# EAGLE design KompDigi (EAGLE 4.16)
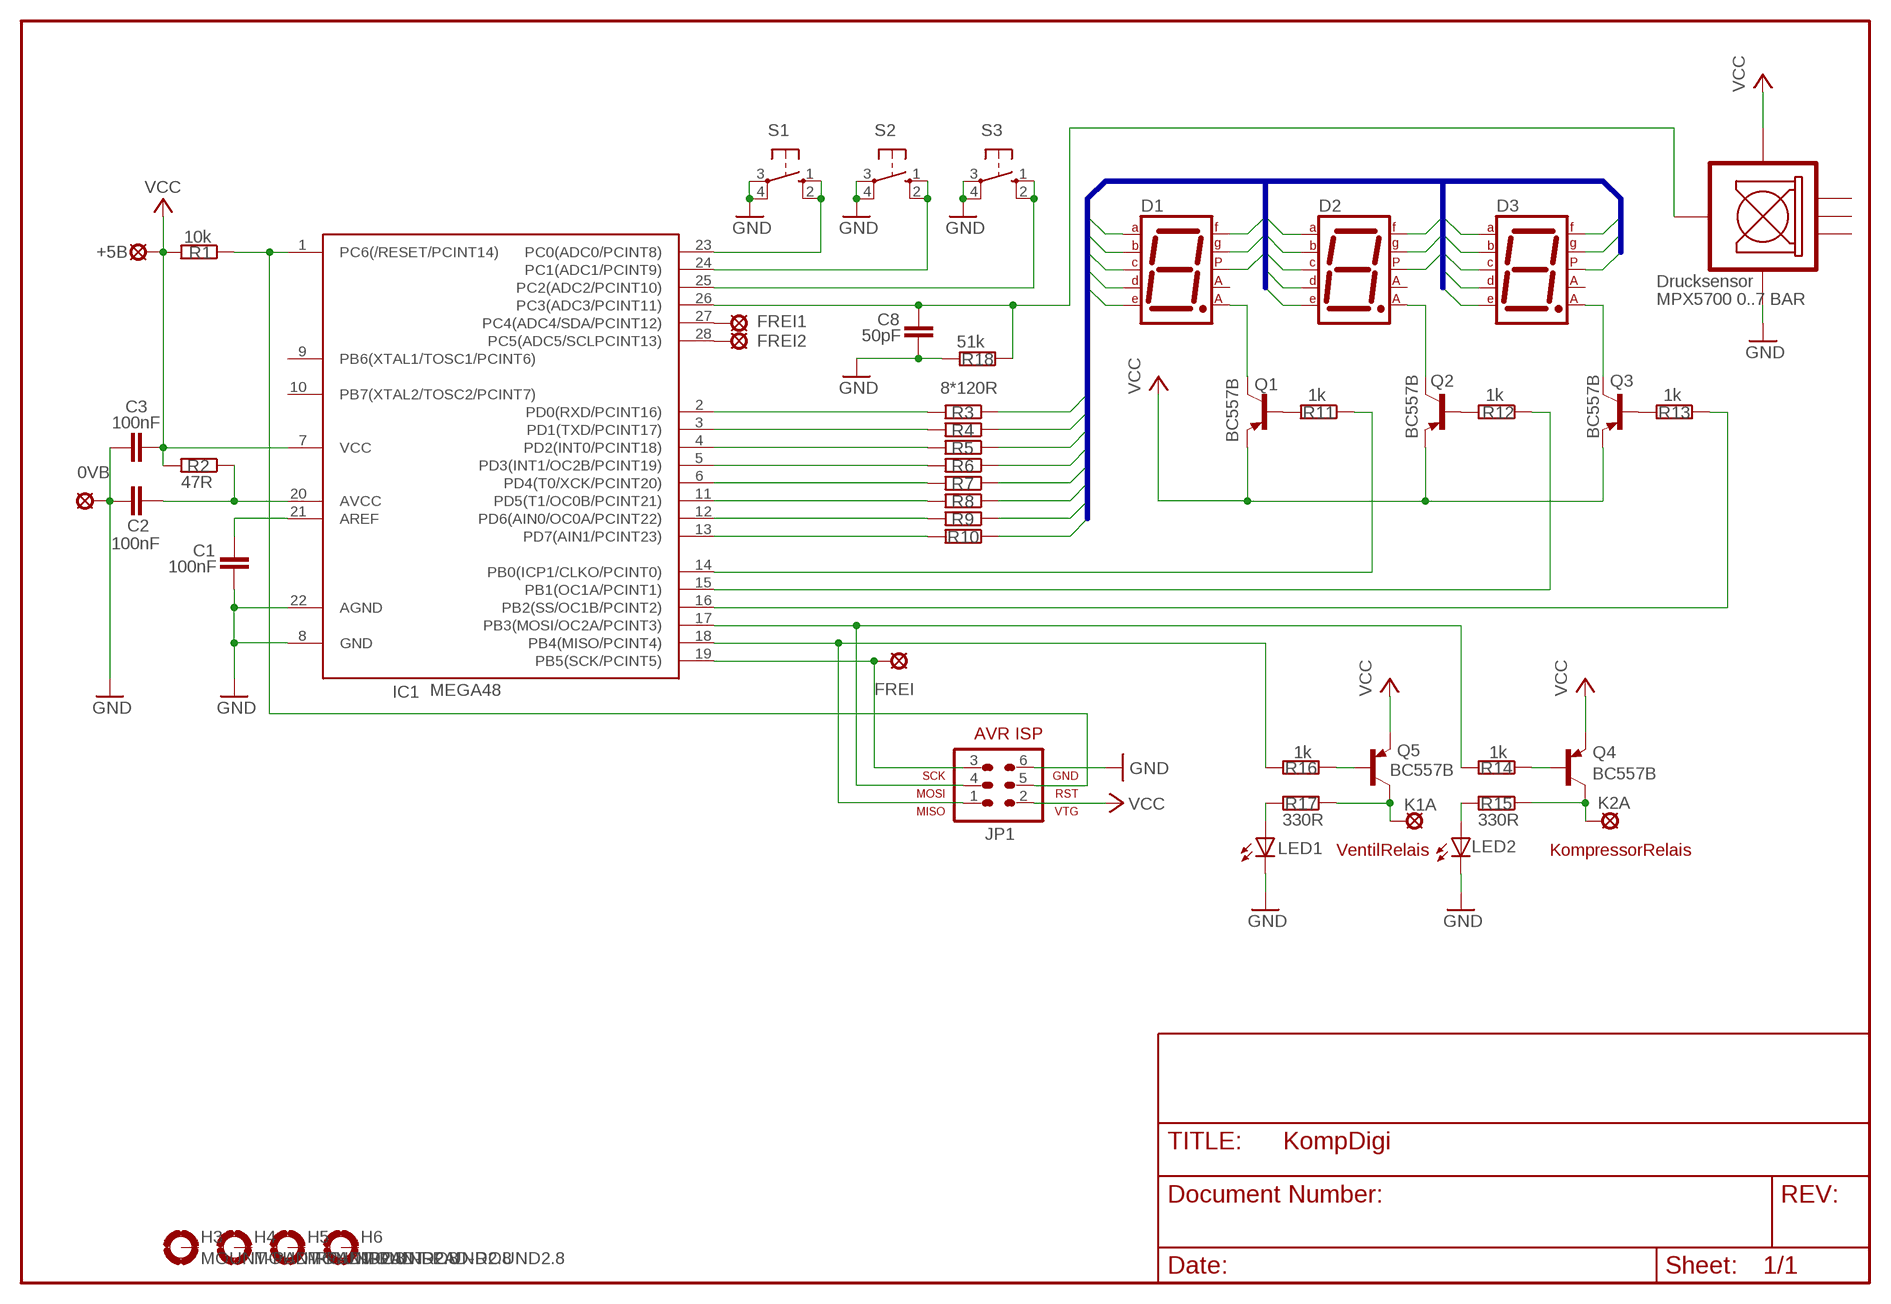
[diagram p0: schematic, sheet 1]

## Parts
0VB  LSP10  [LSP10]
+5B  LSP10  [LSP10]
C1  100nF  C-EU025-025X050  [C025-025X050]
C2  100nF  C-EU025-025X050  [C025-025X050]
C3  100nF  C-EU025-025X050  [C025-025X050]
C8  50pF  C-EU025-024X044  [C025-024X044]
D1  7SEG-CA  [7SEG-13]
D2  7SEG-CA  [7SEG-13]
D3  7SEG-CA  [7SEG-13]
DR1  MPX5700  MPX5700GS  [MPX5700GS]
FREI  LSP10  [LSP10]
FREI1  LSP10  [LSP10]
FREI2  LSP10  [LSP10]
H3  MOUNT-PAD-ROUND2.8  [2,8-PAD]
H4  MOUNT-PAD-ROUND2.8  [2,8-PAD]
H5  MOUNT-PAD-ROUND2.8  [2,8-PAD]
H6  MOUNT-PAD-ROUND2.8  [2,8-PAD]
IC1  MEGA48  MEGA48/88/168-PU  [DIL28-3]
JP1  AVR-ISP-6  [AVR-ISP-6]
K1A  LSP10  [LSP10]
K2A  LSP10  [LSP10]
LED1  LED3MM  [LED3MM]
LED2  LED3MM  [LED3MM]
Q1  BC557B  [TO92-EBC]
Q2  BC557B  [TO92-EBC]
Q3  BC557B  [TO92-EBC]
Q4  BC557B  [TO92-EBC]
Q5  BC557B  [TO92-EBC]
R1  10k  R-EU_0207/7  [0207/7]
R2  47R  R-EU_0207/7  [0207/7]
R3  R-EU_0207/7  [0207/7]
R4  R-EU_0207/7  [0207/7]
R5  R-EU_0207/7  [0207/7]
R6  R-EU_0207/7  [0207/7]
R7  R-EU_0207/7  [0207/7]
R8  R-EU_0207/7  [0207/7]
R9  R-EU_0207/7  [0207/7]
R10  R-EU_0207/7  [0207/7]
R11  1k  R-EU_0207/7  [0207/7]
R12  1k  R-EU_0207/7  [0207/7]
R13  1k  R-EU_0207/7  [0207/7]
R14  1k  R-EU_0207/7  [0207/7]
R15  330R  R-EU_0207/7  [0207/7]
R16  1k  R-EU_0207/7  [0207/7]
R17  330R  R-EU_0207/7  [0207/7]
R18  51k  R-EU_0207/7  [0207/7]
S1  10-XX  [B3F-10XX]
S2  10-XX  [B3F-10XX]
S3  10-XX  [B3F-10XX]

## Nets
A: D1.7(A) D2.7(A) D3.7(A) R3.1
B: D1.6(B) D2.6(B) D3.6(B) R4.1
C: D1.4(C) D2.4(C) D3.4(C) R5.1
D: D1.2(D) D2.2(D) D3.2(D) R6.1
DP: D1.5(DP) D2.5(DP) D3.5(DP) R10.1
E: D1.1(E) D2.1(E) D3.1(E) R7.1
F: D1.9(F) D2.9(F) D3.9(F) R8.1
G: D1.10(G) D2.10(G) D3.10(G) R9.1
GND: 0VB.MP C1.1 C2.1 C3.1 C8.1 DR1.2(GND) IC1.8(GND) IC1.22(AGND) JP1.6 LED1.K(C) LED2.K(C) R18.2 S1.3(P) S1.4(P1) S2.3(P) S2.4(P1) S3.3(P) S3.4(P1)
N$1: D1.8(CA2) Q1.C
N$2: D2.8(CA2) Q2.C
N$3: D3.8(CA2) Q3.C
N$4: C1.2 IC1.21(AREF)
N$5: C2.2 IC1.20(AVCC) R2.1
N$6: IC1.1(PC6(/RESET/PCINT14)) JP1.5 R1.1
N$7: IC1.2(PD0(RXD/PCINT16)) R3.2
N$8: IC1.3(PD1(TXD/PCINT17)) R4.2
N$9: IC1.4(PD2(INT0/PCINT18)) R5.2
N$10: IC1.5(PD3(INT1/OC2B/PCINT19)) R6.2
N$11: IC1.6(PD4(T0/XCK/PCINT20)) R7.2
N$12: IC1.11(PD5(T1/OC0B/PCINT21)) R8.2
N$13: IC1.12(PD6(AIN0/OC0A/PCINT22)) R9.2
N$14: IC1.13(PD7(AIN1/PCINT23)) R10.2
N$15: Q1.B R11.2
N$16: Q2.B R12.2
N$17: Q3.B R13.2
N$18: IC1.14(PB0(ICP1/CLKO/PCINT0)) R11.1
N$19: IC1.15(PB1(OC1A/PCINT1)) R12.1
N$20: IC1.16(PB2(SS/OC1B/PCINT2)) R13.1
N$21: IC1.17(PB3(MOSI/OC2A/PCINT3)) JP1.4 R14.2
N$22: IC1.18(PB4(MISO/PCINT4)) JP1.1 R16.2
N$23: FREI.MP IC1.19(PB5(SCK/PCINT5)) JP1.3
N$24: Q4.B R14.1
N$25: K2A.MP Q4.C R15.1
N$26: IC1.24(PC1(ADC1/PCINT9)) S2.1(S) S2.2(S1)
N$27: IC1.25(PC2(ADC2/PCINT10)) S3.1(S) S3.2(S1)
N$28: IC1.23(PC0(ADC0/PCINT8)) S1.1(S) S1.2(S1)
N$29: LED2.A R15.2
N$30: Q5.B R16.1
N$31: K1A.MP Q5.C R17.1
N$32: LED1.A R17.2
N$33: C8.2 DR1.1(OUT) IC1.26(PC3(ADC3/PCINT11)) R18.1
N$34: FREI1.MP IC1.27(PC4(ADC4/SDA/PCINT12))
N$35: FREI2.MP IC1.28(PC5(ADC5/SCLPCINT13))
VCC: +5B.MP C3.2 DR1.3(VCC) IC1.7(VCC) JP1.2 Q1.E Q2.E Q3.E Q4.E Q5.E R1.2 R2.2
Unconnected: D1.3(CA1) D2.3(CA1) D3.3(CA1) DR1.4(6NC) DR1.5(5NC) DR1.6(4NC) H3.B2,8(MOUNT) H4.B2,8(MOUNT) H5.B2,8(MOUNT) H6.B2,8(MOUNT) IC1.9(PB6(XTAL1/TOSC1/PCINT6)) IC1.10(PB7(XTAL2/TOSC2/PCINT7))

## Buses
SEG:A,B,C,D,E,F,G,DP

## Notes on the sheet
- Drucksensor
- MPX5700 0..7 BAR
- 8*120R
- VentilRelais | KompressorRelais

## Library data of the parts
0VB +5B FREI FREI1 FREI2 K1A K2A = solpad:LSP10: SOLDER PAD
C1-C3 C8 = rcl:C-EU: CAPACITOR, European symbol
D1-D3 = andereBauteile:7SEG-CA: 7-segment DISPLAY single anode, 13 mm
DR1 = mpx5700:MPX5700GS
H3-H6 = holes:MOUNT-PAD-ROUND: MOUNTING PAD, round
IC1 = avr-5-4.16:MEGA48/88/168-PU
JP1 = atmel (2):AVR-ISP-6: AVR ISP-6 Serial Programming Header
LED1 LED2 = led:LED: LED
Q1-Q5 = transistor-pnp:BC557*: PNP Transistror
R1-R18 = rcl:R-EU_: RESISTOR, European symbol
S1-S3 = switch-omron:10-XX: OMRON SWITCH

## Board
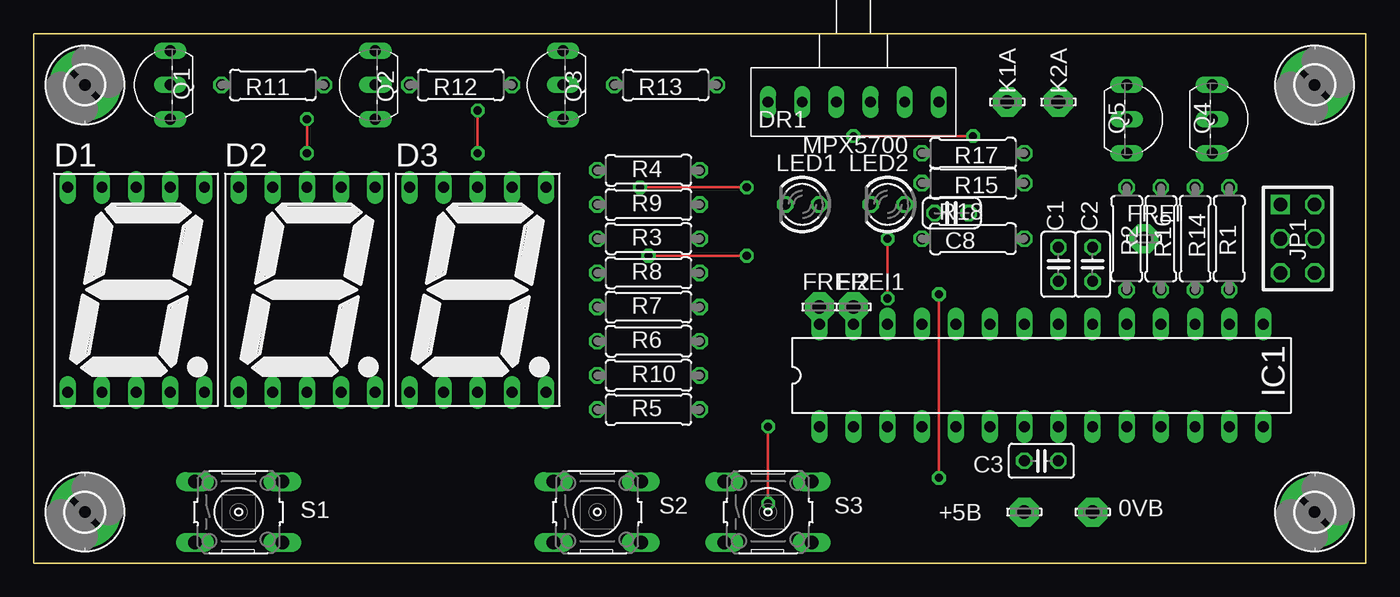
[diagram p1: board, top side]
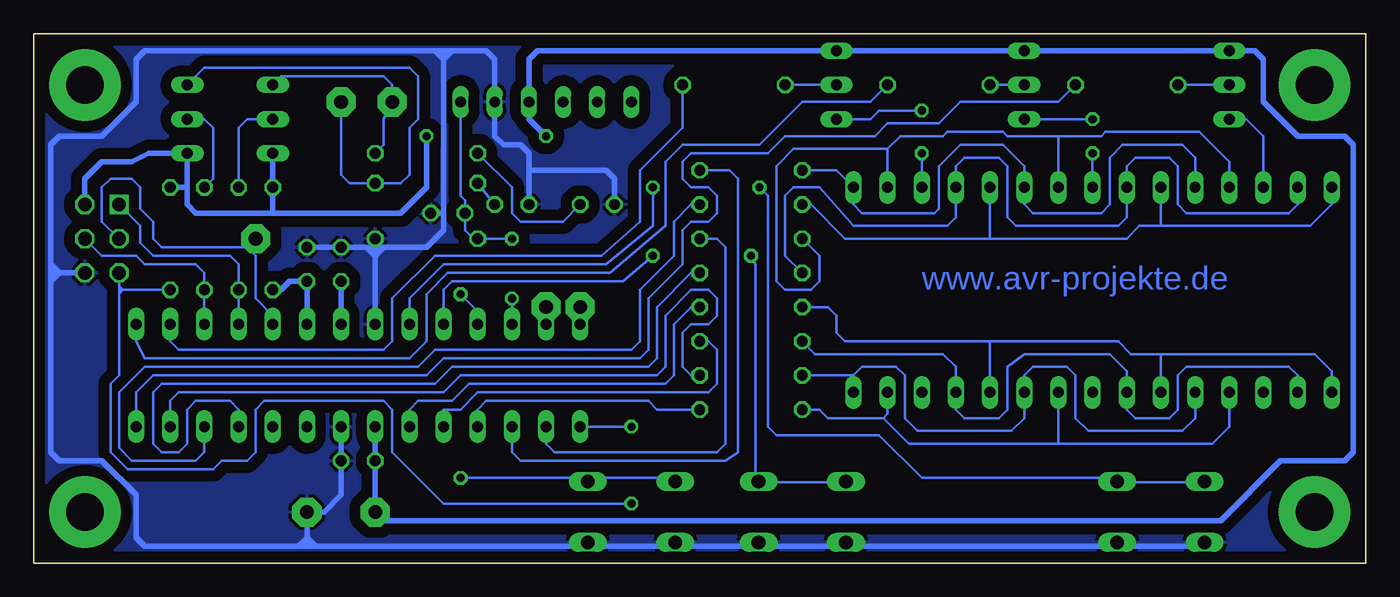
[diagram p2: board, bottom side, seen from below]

Size 99.06 x 39.37 mm. Coordinates in mm from the lower left corner, seen from the top.
Outline: 99.06,0 99.06,39.37 0,39.37 0,0 99.06,0
Copper layers (1*16): Top 0.035mm / dielectric 1.5mm / Bottom 0.035mm
Design rules "ZWILLING": minimum track width 0.2mm, minimum drill 0.5mm, track to track 0.2mm, track to pad 0.2mm, pad to pad 0.15mm, via to via 0.2mm, smd to smd 0mil, copper to edge 0.2mm, drill to drill 0.2mm, minimum pad ring 0.2mm, minimum via ring 0.2mm, stop-mask expansion 0.1mm, vias tented up to drill 0mil, thermal gap 10mil

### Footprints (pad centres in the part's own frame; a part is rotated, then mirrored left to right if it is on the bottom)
LSP10 = drill 1.016 pad 2.159 octagon: MP 0,0
C025-025X050 = drill 0.813 octagon: 1 -1.27,0; 2 1.27,0
C025-024X044 = drill 0.813 octagon: 1 -1.27,0; 2 1.27,0
7SEG-13 = drill 0.813 long: 1 -5.08,-7.62; 2 -2.54,-7.62; 3 0,-7.62; 4 2.54,-7.62; 5 5.08,-7.62; 6 5.08,7.62; 7 2.54,7.62; 8 0,7.62; 9 -2.54,7.62; 10 -5.08,7.62
MPX5700GS = drill 0.8 long: 1 6.35,0; 2 3.81,0; 3 1.27,0; 4 -1.27,0; 5 -3.81,0; 6 -6.35,0
2,8-PAD = drill 2.8 pad 5.334 round: B2,8 0,0
DIL28-3 = drill 0.813 long: 1 -16.51,-3.81; 2 -13.97,-3.81; 3 -11.43,-3.81; 4 -8.89,-3.81; 5 -6.35,-3.81; 6 -3.81,-3.81; 7 -1.27,-3.81; 8 1.27,-3.81; 9 3.81,-3.81; 10 6.35,-3.81; 11 8.89,-3.81; 12 11.43,-3.81; 13 13.97,-3.81; 14 16.51,-3.81; 15 16.51,3.81; 16 13.97,3.81; 17 11.43,3.81; 18 8.89,3.81; 19 6.35,3.81; 20 3.81,3.81; 21 1.27,3.81; 22 -1.27,3.81; 23 -3.81,3.81; 24 -6.35,3.81; 25 -8.89,3.81; 26 -11.43,3.81; 27 -13.97,3.81; 28 -16.51,3.81
AVR-ISP-6 = drill 1.016 square: 1 -2.54,-1.27 | drill 1.016 octagon: 2 -2.54,1.27; 3 0,-1.27; 4 0,1.27; 5 2.54,-1.27; 6 2.54,1.27
LED3MM = drill 0.813 octagon: A -1.27,0; K 1.27,0
TO92-EBC = drill 0.813 long: B 0,-1.27; C -2.54,-1.27; E 2.54,-1.27
0207/7 = drill 0.813 octagon: 1 -3.81,0; 2 3.81,0
B3F-10XX = drill 1.016 long: 1 -3.251,2.261; 2 3.251,2.261; 3 -3.251,-2.261; 4 3.251,-2.261

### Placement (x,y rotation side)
0VB  78.74,3.81 0 top
+5B  73.66,3.81 0 top
C1  76.2,22.23 270 top
C2  78.74,22.23 270 top
C3  74.93,7.62 180 top
C8  68.26,26.04 180 top
D1  7.62,20.32 0 top
D2  20.32,20.32 0 top
D3  33.02,20.32 0 top
DR1  60.96,34.29 0 top
FREI  82.55,24.13 0 top
FREI1  60.96,19.05 0 top
FREI2  58.42,19.05 0 top
H3  3.81,35.56 0 top
H4  3.81,3.81 0 top
H5  95.25,35.56 0 top
H6  95.25,3.81 0 top
IC1  74.93,13.97 0 top
JP1  93.98,24.13 270 top
K1A  72.39,34.29 0 top
K2A  76.2,34.29 0 top
LED1  57.15,26.67 180 top
LED2  63.5,26.67 180 top
Q1  8.89,35.56 90 top
Q2  24.13,35.56 90 top
Q3  38.1,35.56 90 top
Q4  88.9,33.02 270 top
Q5  82.55,33.02 270 top
R1  88.9,24.13 90 top
R2  81.28,24.13 90 top
R3  45.72,24.13 0 top
R4  45.72,29.21 0 top
R5  45.72,11.43 0 top
R6  45.72,16.51 0 top
R7  45.72,19.05 0 top
R8  45.72,21.59 0 top
R9  45.72,26.67 0 top
R10  45.72,13.97 0 top
R11  17.78,35.56 180 top
R12  31.75,35.56 180 top
R13  46.99,35.56 180 top
R14  86.36,24.13 270 top
R15  69.85,28.26 180 top
R16  83.82,24.13 270 top
R17  69.85,30.48 180 top
R18  69.85,24.13 0 top
S1  15.24,3.81 0 top
S2  41.91,3.81 0 top
S3  54.61,3.81 0 top

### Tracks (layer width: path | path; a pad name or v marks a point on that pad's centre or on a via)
A
  Bottom 0.203: D1.7 10.16,29.84 12.38,32.07 19.37,32.07 19.68,31.75 22.86,31.75 | 35.56,30.8 42.55,30.8 43.81,29.53 43.81,20.95 43.18,20.32 41.27,20.32 40.64,20.95 40.64,22.86 R3.1 | 35.56,30.8 D3.7 | 22.86,31.75 26.67,31.75 26.99,32.07 31.11,32.07 31.43,31.75 34.61,31.75 35.56,30.8 | 22.86,31.75 D2.7
B
  Bottom 0.203: D1.6 12.7,30.16 13.65,31.11 18.1,31.11 19.05,30.16 19.05,26.67 19.68,26.04 24.77,26.04 25.4,26.67 D2.6 25.4,29.53 26.99,31.11 30.16,31.11 31.75,29.53 31.75,26.35 32.07,26.04 37.47,26.04 38.1,26.67 D3.6 39.37,29.21 R4.1
C
  Bottom 0.203: D1.4 10.16,10.16 11.43,8.89 22.86,8.89 | 22.86,8.89 33.97,8.89 35.88,10.79 | 22.86,8.89 D2.4 | R5.1 40.64,11.43 40.01,10.79 35.88,10.79 | D3.4 35.56,11.11 35.88,10.79
D
  Bottom 0.203: D1.2 5.08,13.97 5.71,14.61 13.34,14.61 13.97,13.97 13.97,11.43 14.61,10.79 17.14,10.79 17.78,11.43 D2.2 17.78,14.29 19.05,15.56 25.4,15.56 26.67,14.61 26.67,11.43 27.3,10.79 29.84,10.79 30.48,11.43 D3.2 30.48,14.61 31.43,15.56 40.96,15.56 R6.1
DP
  Bottom 0.203: D1.5 12.7,10.79 13.65,9.84 20.64,9.84 21.59,10.79 21.59,13.97 22.23,14.61 24.77,14.61 25.4,13.97 D2.5 25.4,10.79 26.35,9.84 33.34,9.84 34.29,10.79 34.29,13.97 34.92,14.61 37.47,14.61 38.1,13.97 | 38.1,13.97 D3.5 | 38.1,13.97 R10.1
E
  Bottom 0.203: D1.1 2.54,14.29 3.81,15.56 15.24,15.56 | R7.1 40.01,19.05 39.37,18.41 39.37,17.14 38.73,16.51 27.94,16.51 | 15.24,15.56 17.46,15.56 18.41,16.51 27.94,16.51 | 27.94,16.51 D3.1 | 15.24,15.56 D2.1
F
  Bottom 0.203: D1.9 5.08,26.67 5.71,26.04 13.34,26.04 13.97,26.67 13.97,29.53 14.61,30.16 17.14,30.16 17.78,29.53 D2.9 17.78,25.72 18.41,25.08 26.04,25.08 26.67,25.72 26.67,29.53 27.3,30.16 29.84,30.16 30.48,29.53 D3.9 30.48,25.72 31.11,25.08 38.1,25.08 40.64,27.94 42.55,27.94 43.18,27.3 43.18,22.86 R8.1
G
  Bottom 0.203: D1.10 2.54,26.67 4.13,25.08 15.24,25.08 | 15.24,25.08 16.83,25.08 17.78,24.13 27.94,24.13 | 27.94,24.13 38.73,24.13 41.27,26.67 R9.1 | 27.94,24.13 D3.10 | 15.24,25.08 D2.10
GND
  Bottom 0.203: 78.11,1.27 78.74,1.27 79.38,1.27 | 18.41,1.27 18.49,1.35 | 38.73,1.27 38.66,1.35 | 45.09,1.27 45.16,1.35 | S3.3 51.36,1.35 51.44,1.27 | S3.4 57.86,1.35 57.78,1.27
  Bottom 0.406: S1.3 11.99,1.98 12.7,1.27 18.41,1.27 38.73,1.27 45.09,1.27 51.44,1.27 57.78,1.27 78.11,1.27 | 79.38,1.27 90.81,1.27 91.44,1.91 91.44,5.08 93.98,7.62 97.16,7.62 97.79,8.26 97.79,20.95 | 97.79,20.95 97.79,21.59 | 97.79,21.59 97.79,22.23 | 97.79,22.23 97.79,31.11 97.16,31.75 93.98,31.75 91.44,34.29 91.44,37.47 90.81,38.1 69.22,38.1 | 69.22,38.1 68.58,38.1 | 68.58,38.1 67.94,38.1 | 67.94,38.1 65.41,38.1 64.77,37.47 DR1.2 64.77,31.75 64.14,31.11 62.87,31.11 62.23,30.48 62.23,29.21 | 18.49,1.35 S1.4 | 38.66,1.35 S2.3 | 45.16,1.35 S2.4 | IC1.8 C3.1 76.2,5.08 77.47,3.81 0VB.MP 78.74,1.91 | C2.1 C1.1 74.3,23.5 | 78.74,1.27 78.74,1.91 | 62.23,29.21 LED2.K | 62.23,29.21 56.52,29.21 55.88,28.57 LED1.K | 73.03,23.5 69.85,23.5 68.58,24.77 68.58,26.04 | 73.03,23.5 73.66,23.5 | 73.66,23.5 73.66,22.86 | 73.66,22.86 IC1.22 | 68.58,38.1 68.58,37.47 | 68.58,37.47 68.58,26.04 | 73.66,23.5 74.3,23.5 | 73.66,22.86 74.3,23.5 | 73.03,23.5 73.66,22.86 | 68.58,37.47 67.94,38.1 | 69.22,38.1 68.58,37.47 | 97.79,22.23 97.16,21.59 97.79,20.95 | 78.11,1.27 78.74,1.91 | 78.11,1.27 79.38,1.27 | 78.74,1.91 79.38,1.27 | 73.66,23.5 R18.2 | 68.58,26.04 C8.1 | 97.79,21.59 JP1.6
  pour Bottom (isolate 0.813): -1.27,-1.27 100.33,-1.27 100.33,40.64 -1.27,40.64
N$1
  Bottom 0.203: D1.8 7.62,31.75 8.89,33.02 Q1.C
N$2  (via drill 0.6 pad 1.02)
  Top 0.203: v20.32,30.48 v20.32,33.02
  Bottom 0.203: D2.8 v20.32,30.48 | v20.32,33.02 Q2.C
N$3  (via drill 0.6 pad 1.02)
  Top 0.203: v33.02,30.48 v33.02,33.66
  Bottom 0.203: D3.8 v33.02,30.48 | v33.02,33.66 36.2,33.66 36.83,33.02 Q3.C
N$4
  Bottom 0.406: IC1.21 C1.2
N$5
  Bottom 0.406: IC1.20 C2.2 80.01,20.95 80.64,20.32 R2.1
N$6  (via drill 0.6 pad 1.02)
  Top 0.203: v54.61,4.45 v54.61,10.16
  Bottom 0.203: v54.61,4.45 68.58,4.45 72.39,8.26 72.39,11.43 73.03,12.06 81.92,12.06 82.55,11.43 82.55,8.26 83.19,7.62 85.09,7.62 85.72,6.99 92.08,6.99 93.34,8.26 93.34,13.34 92.71,13.97 92.71,20 | 92.71,20 92.71,20.32 | 92.71,20.32 92.71,20.64 | 92.71,20.64 JP1.5 | 92.71,20.32 92.39,20.32 | 92.39,20.32 R1.1 | 92.71,20.64 92.39,20.32 | 92.71,20 92.71,20.64 | 92.71,20 92.39,20.32 | v54.61,10.16 IC1.1
N$7
  Bottom 0.203: R3.2 48.26,24.13 47.62,23.5 47.62,8.89 48.26,8.26 60.33,8.26 60.96,8.89 IC1.2
N$8
  Bottom 0.203: R4.2 47.31,29.21 46.67,28.57 46.67,8.26 47.62,7.62 62.87,7.62 63.5,8.26 IC1.3
N$9
  Bottom 0.203: IC1.4 66.04,11.43 65.41,12.06 53.34,12.06 52.7,11.43 R5.2
N$10
  Bottom 0.203: IC1.5 68.58,11.43 67.31,11.43 66.04,12.7 48.9,12.7 48.26,13.34 48.26,15.88 48.9,16.51 R6.2
N$11
  Bottom 0.203: IC1.6 71.12,11.43 70.48,12.06 67.94,12.06 66.67,13.34 52.07,13.34 51.44,13.97 51.44,17.78 50.16,19.05 R7.2
N$12
  Bottom 0.203: R8.2 50.16,21.59 52.7,19.05 52.7,15.24 53.34,14.61 67.94,14.61 69.22,13.34 89.53,13.34 90.17,12.7 90.17,8.89 89.53,8.26 88.27,8.26 87.63,8.89 87.63,11.43 87,12.06 84.45,12.06 83.82,11.43 IC1.11
N$13
  Bottom 0.203: R9.2 50.16,26.67 51.44,25.4 51.44,22.86 53.98,20.32 53.98,16.51 54.61,15.88 69.22,15.88 70.48,14.61 90.81,14.61 92.71,12.7 92.71,8.57 91.76,7.62 87,7.62 86.36,8.26 IC1.12
N$14
  Bottom 0.203: R10.2 50.16,13.97 50.8,14.61 50.8,17.14 50.16,17.78 48.9,17.78 48.26,18.41 48.26,19.68 48.9,20.32 50.16,20.32 52.07,18.41 52.07,14.61 52.7,13.97 67.31,13.97 68.58,12.7 88.27,12.7 88.9,12.06 IC1.13
N$15
  Bottom 0.203: Q1.B R11.2
N$16
  Bottom 0.203: Q2.B R12.2
N$17
  Bottom 0.203: Q3.B R13.2
N$18
  Bottom 0.203: IC1.14 91.44,12.7 90.17,13.97 69.85,13.97 68.58,15.24 53.98,15.24 53.34,15.88 53.34,19.68 50.8,22.23 50.8,24.77 50.16,25.4 48.9,25.4 48.26,26.04 48.26,27.3 48.9,27.94 50.16,27.94 50.8,28.57 50.8,29.84 50.16,30.48 44.45,30.48 43.18,31.75 36.51,31.75 35.56,32.7 31.75,32.7 30.16,34.29 22.86,34.29 R11.1
N$19
  Bottom 0.203: R12.1 36.83,34.29 41.91,34.29 45.09,31.11 50.8,31.11 52.07,29.84 52.07,25.08 56.2,21.59 68.26,21.59 69.85,20 69.85,16.51 71.12,15.24 90.81,15.24 91.44,16.51 IC1.15
N$20
  Bottom 0.203: R13.1 50.8,32.38 53.98,29.21 53.98,25.4 56.83,22.86 69.22,22.86 72.39,19.68 72.39,16.51 73.03,15.88 88.27,15.88 88.9,16.51 IC1.16
N$21
  Bottom 0.203: IC1.17 R14.2 86.36,21.59 87,22.23 90.81,22.23 91.44,22.86 93.98,22.86 JP1.4
N$22
  Bottom 0.203: IC1.18 R16.2 83.82,22.23 84.45,22.86 90.17,22.86 91.12,23.81 91.12,25.08 JP1.1
N$23
  Bottom 0.203: IC1.19 81.28,18.41 82.55,19.68 82.55,22.86 83.19,23.5 89.53,23.5 90.17,24.13 90.17,25.4 91.12,26.35 91.12,27.94 91.76,28.57 93.34,28.57 93.98,27.94 93.98,25.4 JP1.3
  Bottom 0.406: 83.19,23.5 FREI.MP
N$24
  Bottom 0.203: Q4.B 86.36,33.02 85.72,32.38 85.72,28.57 R14.1
N$25
  Bottom 0.203: Q4.C 86.36,36.83 71.12,36.83 70.48,36.2 70.48,33.02 71.12,32.38 71.12,28.89 71.75,28.26 R15.1 75.56,28.26 76.2,28.89 K2A.MP
N$26  (via drill 0.6 pad 1.02)
  Top 0.203: v45.72,22.86 v53.02,22.86
  Bottom 0.203: IC1.24 68.58,20.32 67.94,20.95 55.24,20.95 v53.02,22.86 | v45.72,22.86 45.4,22.23 45.4,6.35 45.16,6.11 S2.2 45.12,6.03 38.7,6.03 S2.1
N$27  (via drill 0.6 pad 1.02)
  Top 0.203: v67.31,6.35 v67.31,20
  Bottom 0.203: S3.1 51.44,6.15 51.44,6.35 57.58,6.35 S3.2 58.06,6.07 58.1,6.03 58.42,6.35 v67.31,6.35 | IC1.25 66.04,18.73 v67.31,20
N$28  (via drill 0.6 pad 1.02)
  Top 0.203: v45.09,27.94 v53.02,27.94
  Bottom 0.203: IC1.23 71.12,19.68 68.58,22.23 56.52,22.23 53.02,25.08 v53.02,27.94 | v45.09,27.94 44.45,27.3 44.45,10.16 43.81,9.53 36.2,9.53 33.02,6.35 19.05,6.35 18.73,6.03 18.41,6.03 | S1.1 12.03,6.03 18.41,6.03 | 18.41,6.03 18.45,6.03 S1.2
N$29
  Bottom 0.203: LED2.A R15.2
N$30
  Bottom 0.203: R16.1 83.82,32.38 83.19,33.02 Q5.B
N$31
  Bottom 0.203: Q5.C 80.64,36.2 73.03,36.2 72.39,35.56 K1A.MP 73.03,33.02 73.03,31.11 R17.1
N$32
  Bottom 0.203: LED1.A 59.69,25.4 62.87,25.4 63.5,26.04 63.5,27.94 R17.2
N$33  (via drill 0.6 pad 1.02)
  Top 0.203: v63.5,19.68 v63.5,24.13
  Bottom 0.203: IC1.26 v63.5,19.68 | v63.5,24.13 R18.1 66.36,24.13 66.99,24.77 C8.2 66.99,26.99 67.31,27.3 DR1.1
N$34
  Bottom 0.406: FREI1.MP IC1.27
N$35
  Bottom 0.406: FREI2.MP IC1.28
VCC  (via drill 0.6 pad 1.02)
  Top 0.203: v60.96,31.75 v69.85,31.75
  Bottom 0.203: DR1.3 62.23,33.02
  Bottom 0.406: DR1.3 62.23,37.47 61.59,38.1 Q3.E Q2.E Q1.E 8.26,38.1 7.62,37.47 7.62,34.29 5.08,31.75 1.59,31.75 0.95,31.11 0.95,8.26 1.59,7.62 6.35,7.62 10.79,3.17 73.03,3.17 +5B.MP C3.2 IC1.7 | 62.23,33.02 v60.96,31.75 | 81.28,26.04 87,26.04 87.63,26.67 87.63,27.94 | 87.63,27.94 Q4.E 90.49,30.48 91.76,29.84 93.98,29.84 95.25,28.57 JP1.2 | 81.28,26.04 R2.2 Q5.E | 87.63,27.94 R1.2 | 81.28,26.04 71.75,26.04 69.85,27.94 v69.85,31.75

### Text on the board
Bottom: www.avr-projekte.de
tValues: 8*120R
